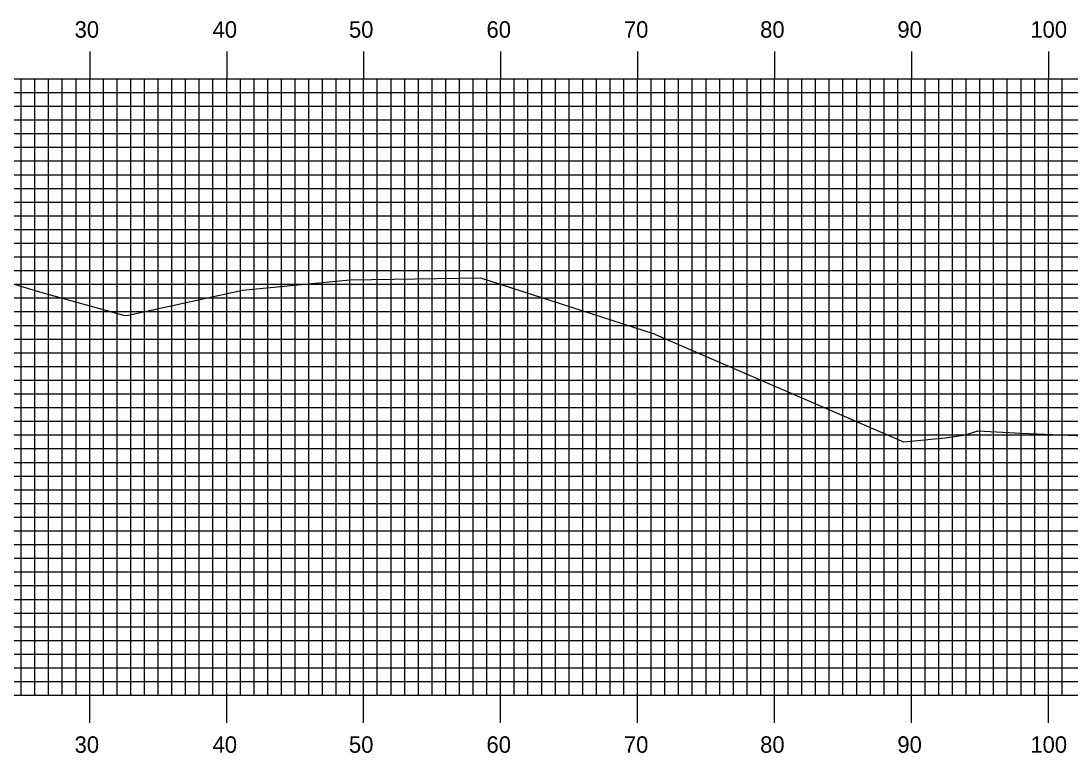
# Model space of a CAD drawing. Extents: x 860652 to 860995, y 364765 to 364985.
# Drawn here: x 860842.4 to 860919.1, y 364839.1 to 364892.5 of the extents above; entities that cross this region are included whole.
import ezdxf

# ---------------------------------------------------------------- set-up
doc = ezdxf.new("R2010")
doc.units = 0
for name, color, linetype in [('H_V ANNOTATION', 7, 'Continuous'), ('MAJOR', 7, 'Continuous'), ('MINOR', 7, 'Continuous'), ('S_Roadway_Centerline', 7, 'Continuous')]:
    doc.layers.add(name, color=color, linetype=linetype)

msp = doc.modelspace()

# ---------------------------------------------------------------- linework, layer by layer
at = {"layer": 'MAJOR'}
for p, q in [((860847.412, 364890.306), (860847.412, 364888.302)), ((860857.412, 364890.306), (860857.412, 364888.302)), ((860867.412, 364890.306), (860867.412, 364888.302)), ((860877.412, 364890.306), (860877.412, 364888.302)), ((860887.412, 364890.306), (860887.412, 364888.302)), ((860897.412, 364890.306), (860897.412, 364888.302)), ((860907.412, 364890.306), (860907.412, 364888.302)), ((860917.412, 364890.306), (860917.412, 364888.302)), ((860677.412, 364888.302), (860957.412, 364888.302)), ((860677.412, 364888.302), (860957.412, 364888.302)), ((860847.412, 364843.302), (860847.412, 364888.302)), ((860857.412, 364843.302), (860857.412, 364888.302)), ((860867.412, 364843.302), (860867.412, 364888.302)), ((860877.412, 364843.302), (860877.412, 364888.302)), ((860887.412, 364843.302), (860887.412, 364888.302)), ((860897.412, 364843.302), (860897.412, 364888.302)), ((860907.412, 364843.302), (860907.412, 364888.302)), ((860917.412, 364843.302), (860917.412, 364888.302)), ((860677.412, 364883.302), (860957.412, 364883.302)), ((860677.412, 364878.302), (860957.412, 364878.302)), ((860677.412, 364873.302), (860957.412, 364873.302)), ((860677.412, 364868.302), (860957.412, 364868.302)), ((860677.412, 364863.302), (860957.412, 364863.302)), ((860677.412, 364858.302), (860957.412, 364858.302)), ((860677.412, 364853.302), (860957.412, 364853.302)), ((860677.412, 364848.302), (860957.412, 364848.302)), ((860677.412, 364843.302), (860957.412, 364843.302)), ((860677.412, 364843.302), (860957.412, 364843.302)), ((860847.412, 364841.298), (860847.412, 364843.302)), ((860857.412, 364841.298), (860857.412, 364843.302)), ((860867.412, 364841.298), (860867.412, 364843.302)), ((860877.412, 364841.298), (860877.412, 364843.302)), ((860887.412, 364841.298), (860887.412, 364843.302)), ((860897.412, 364841.298), (860897.412, 364843.302)), ((860907.412, 364841.298), (860907.412, 364843.302)), ((860917.412, 364841.298), (860917.412, 364843.302))]:
    msp.add_line(p, q, dxfattribs=at)
at = {"layer": 'MINOR'}
for p, q in [((860842.412, 364843.302), (860842.412, 364888.302)), ((860843.412, 364843.302), (860843.412, 364888.302)), ((860844.412, 364843.302), (860844.412, 364888.302)), ((860845.412, 364843.302), (860845.412, 364888.302)), ((860846.412, 364843.302), (860846.412, 364888.302)), ((860848.412, 364843.302), (860848.412, 364888.302)), ((860849.412, 364843.302), (860849.412, 364888.302)), ((860850.412, 364843.302), (860850.412, 364888.302)), ((860851.412, 364843.302), (860851.412, 364888.302)), ((860852.412, 364843.302), (860852.412, 364888.302)), ((860853.412, 364843.302), (860853.412, 364888.302)), ((860854.412, 364843.302), (860854.412, 364888.302)), ((860855.412, 364843.302), (860855.412, 364888.302)), ((860856.412, 364843.302), (860856.412, 364888.302)), ((860858.412, 364843.302), (860858.412, 364888.302)), ((860859.412, 364843.302), (860859.412, 364888.302)), ((860860.412, 364843.302), (860860.412, 364888.302)), ((860861.412, 364843.302), (860861.412, 364888.302)), ((860862.412, 364843.302), (860862.412, 364888.302)), ((860863.412, 364843.302), (860863.412, 364888.302)), ((860864.412, 364843.302), (860864.412, 364888.302)), ((860865.412, 364843.302), (860865.412, 364888.302)), ((860866.412, 364843.302), (860866.412, 364888.302)), ((860868.412, 364843.302), (860868.412, 364888.302)), ((860869.412, 364843.302), (860869.412, 364888.302)), ((860870.412, 364843.302), (860870.412, 364888.302)), ((860871.412, 364843.302), (860871.412, 364888.302)), ((860872.412, 364843.302), (860872.412, 364888.302)), ((860873.412, 364843.302), (860873.412, 364888.302)), ((860874.412, 364843.302), (860874.412, 364888.302)), ((860875.412, 364843.302), (860875.412, 364888.302)), ((860876.412, 364843.302), (860876.412, 364888.302)), ((860878.412, 364843.302), (860878.412, 364888.302)), ((860879.412, 364843.302), (860879.412, 364888.302)), ((860880.412, 364843.302), (860880.412, 364888.302)), ((860881.412, 364843.302), (860881.412, 364888.302)), ((860882.412, 364843.302), (860882.412, 364888.302)), ((860883.412, 364843.302), (860883.412, 364888.302)), ((860884.412, 364843.302), (860884.412, 364888.302)), ((860885.412, 364843.302), (860885.412, 364888.302)), ((860886.412, 364843.302), (860886.412, 364888.302)), ((860888.412, 364843.302), (860888.412, 364888.302)), ((860889.412, 364843.302), (860889.412, 364888.302)), ((860890.412, 364843.302), (860890.412, 364888.302)), ((860891.412, 364843.302), (860891.412, 364888.302)), ((860892.412, 364843.302), (860892.412, 364888.302)), ((860893.412, 364843.302), (860893.412, 364888.302)), ((860894.412, 364843.302), (860894.412, 364888.302)), ((860895.412, 364843.302), (860895.412, 364888.302)), ((860896.412, 364843.302), (860896.412, 364888.302)), ((860898.412, 364843.302), (860898.412, 364888.302)), ((860899.412, 364843.302), (860899.412, 364888.302)), ((860900.412, 364843.302), (860900.412, 364888.302)), ((860901.412, 364843.302), (860901.412, 364888.302)), ((860902.412, 364843.302), (860902.412, 364888.302)), ((860903.412, 364843.302), (860903.412, 364888.302)), ((860904.412, 364843.302), (860904.412, 364888.302)), ((860905.412, 364843.302), (860905.412, 364888.302)), ((860906.412, 364843.302), (860906.412, 364888.302)), ((860908.412, 364843.302), (860908.412, 364888.302)), ((860909.412, 364843.302), (860909.412, 364888.302)), ((860910.412, 364843.302), (860910.412, 364888.302)), ((860911.412, 364843.302), (860911.412, 364888.302)), ((860912.412, 364843.302), (860912.412, 364888.302)), ((860913.412, 364843.302), (860913.412, 364888.302)), ((860914.412, 364843.302), (860914.412, 364888.302)), ((860915.412, 364843.302), (860915.412, 364888.302)), ((860916.412, 364843.302), (860916.412, 364888.302)), ((860918.412, 364843.302), (860918.412, 364888.302)), ((860677.412, 364887.302), (860957.412, 364887.302)), ((860677.412, 364886.302), (860957.412, 364886.302)), ((860677.412, 364885.302), (860957.412, 364885.302)), ((860677.412, 364884.302), (860957.412, 364884.302)), ((860677.412, 364882.302), (860957.412, 364882.302)), ((860677.412, 364881.302), (860957.412, 364881.302)), ((860677.412, 364880.302), (860957.412, 364880.302)), ((860677.412, 364879.302), (860957.412, 364879.302)), ((860677.412, 364877.302), (860957.412, 364877.302)), ((860677.412, 364876.302), (860957.412, 364876.302)), ((860677.412, 364875.302), (860957.412, 364875.302)), ((860677.412, 364874.302), (860957.412, 364874.302)), ((860677.412, 364872.302), (860957.412, 364872.302)), ((860677.412, 364871.302), (860957.412, 364871.302)), ((860677.412, 364870.302), (860957.412, 364870.302)), ((860677.412, 364869.302), (860957.412, 364869.302)), ((860677.412, 364867.302), (860957.412, 364867.302)), ((860677.412, 364866.302), (860957.412, 364866.302)), ((860677.412, 364865.302), (860957.412, 364865.302)), ((860677.412, 364864.302), (860957.412, 364864.302)), ((860677.412, 364862.302), (860957.412, 364862.302)), ((860677.412, 364861.302), (860957.412, 364861.302)), ((860677.412, 364860.302), (860957.412, 364860.302)), ((860677.412, 364859.302), (860957.412, 364859.302)), ((860677.412, 364857.302), (860957.412, 364857.302)), ((860677.412, 364856.302), (860957.412, 364856.302)), ((860677.412, 364855.302), (860957.412, 364855.302)), ((860677.412, 364854.302), (860957.412, 364854.302)), ((860677.412, 364852.302), (860957.412, 364852.302)), ((860677.412, 364851.302), (860957.412, 364851.302)), ((860677.412, 364850.302), (860957.412, 364850.302)), ((860677.412, 364849.302), (860957.412, 364849.302)), ((860677.412, 364847.302), (860957.412, 364847.302)), ((860677.412, 364846.302), (860957.412, 364846.302)), ((860677.412, 364845.302), (860957.412, 364845.302)), ((860677.412, 364844.302), (860957.412, 364844.302))]:
    msp.add_line(p, q, dxfattribs=at)
at = {"layer": 'S_Roadway_Centerline'}
msp.add_lwpolyline([(860834.52, 364875.531), (860843.915, 364872.696), (860849.867, 364871.043), (860850.125, 364871.011), (860858.568, 364872.874), (860866.416, 364873.623), (860875.937, 364873.761), (860888.541, 364869.714), (860888.592, 364869.698), (860888.774, 364869.621), (860906.841, 364861.798), (860909.883, 364862.09), (860911.386, 364862.308), (860912.253, 364862.594), (860915.451, 364862.44), (860921.729, 364862.166), (860929.067, 364862.166), (860933.518, 364862.194), (860938.619, 364861.948), (860950.534, 364861.493), (860957.152, 364861.409), (860957.412, 364861.399)], dxfattribs=at)

# ---------------------------------------------------------------- texts
at = {"layer": 'H_V ANNOTATION'}
for s, p in [('30', (860846.31, 364891.302)), ('40', (860856.385, 364891.302)), ('50', (860866.342, 364891.302)), ('60', (860876.385, 364891.302)), ('70', (860886.417, 364891.302)), ('80', (860896.363, 364891.302)), ('90', (860906.385, 364891.302)), ('100', (860916.096, 364891.302)), ('30', (860846.31, 364839.102)), ('40', (860856.385, 364839.102)), ('50', (860866.342, 364839.102)), ('60', (860876.385, 364839.102)), ('70', (860886.417, 364839.102)), ('80', (860896.363, 364839.102)), ('90', (860906.385, 364839.102)), ('100', (860916.096, 364839.102))]:
    msp.add_text(s, height=1.2, dxfattribs=at).set_placement(p)

doc.saveas('drawing.dxf')
